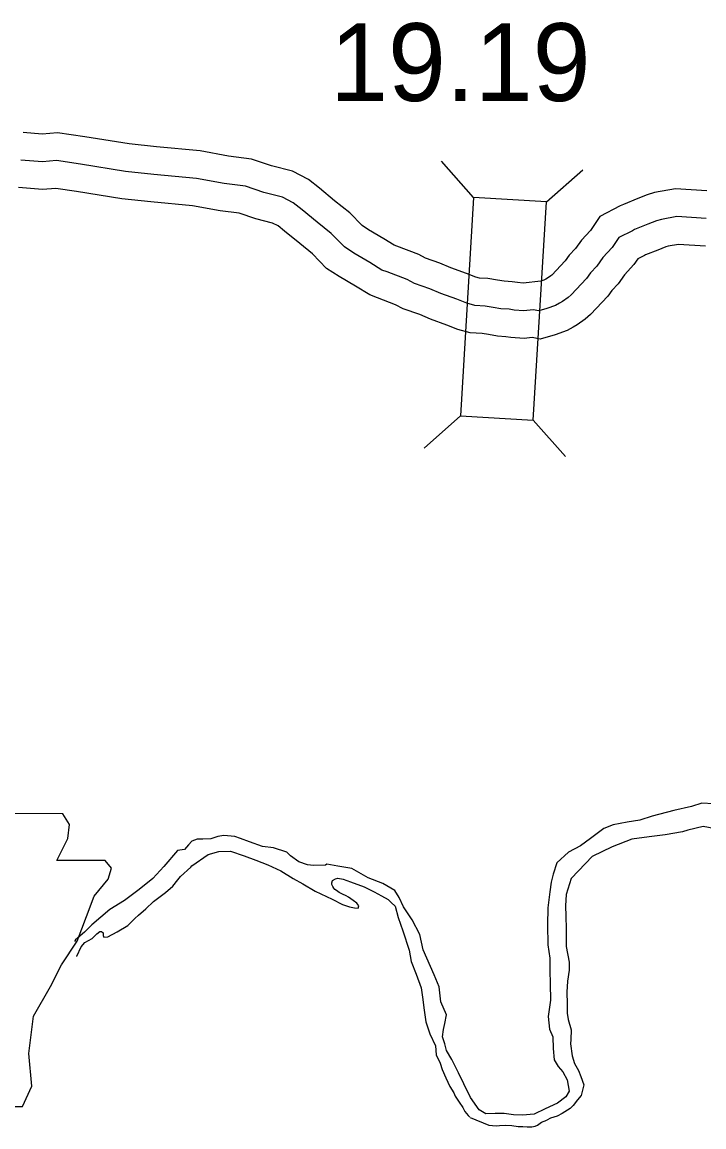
# Model space of a CAD drawing. Extents: x -83719 to 153526, y -11835 to 11446.
# Drawn here: x -4598 to -4474.7, y -2819.1 to -2619 of the extents above; entities that cross this region are included whole.
import ezdxf

# ---------------------------------------------------------------- set-up
doc = ezdxf.new("R2010")
doc.units = 0
for name, color, linetype in [('Level 10', 7, 'Continuous'), ('Level 20', 7, 'Continuous'), ('Level 21', 7, 'Continuous'), ('Level 58', 7, 'Continuous'), ('Level 59', 7, 'Continuous'), ('Level 9', 7, 'Continuous')]:
    doc.layers.add(name, color=color, linetype=linetype)

msp = doc.modelspace()

# ---------------------------------------------------------------- linework, layer by layer
at = {"layer": 'Level 10'}
for points in [[(-4474.15, -2649.59), (-4479.82, -2649.21), (-4483.58, -2649.87), (-4484.91, -2650.3), (-4486.63, -2650.97), (-4489.23, -2652.01), (-4489.85, -2652.3), (-4493.51, -2654.19), (-4495.21, -2656.72), (-4496.82, -2658.48), (-4497.93, -2660.03), (-4499.06, -2661.24), (-4499.78, -2662.23), (-4502.21, -2664.82), (-4502.35, -2664.95), (-4502.96, -2665.36), (-4503.28, -2665.55), (-4503.64, -2665.75), (-4504.17, -2665.95), (-4507.34, -2666.26), (-4508.42, -2666.18), (-4509.39, -2666.03), (-4510.82, -2665.94), (-4511.99, -2665.73), (-4513.74, -2665.46), (-4515.28, -2665.38), (-4515.94, -2665.18), (-4517.63, -2664.51), (-4520.44, -2663.52), (-4522.45, -2662.64), (-4525.02, -2661.77), (-4526.25, -2661.09), (-4530.21, -2659.56), (-4530.73, -2659.38), (-4532.55, -2658.25), (-4535.36, -2656.6), (-4536.52, -2655.84), (-4538.74, -2653.57), (-4541.48, -2651.36), (-4544.22, -2649.11), (-4546.19, -2647.53), (-4549.09, -2645.99), (-4552.9, -2645.04), (-4556.49, -2643.83), (-4560.68, -2643.28), (-4565.81, -2642.35), (-4573.7, -2641.61), (-4578.63, -2641.08), (-4586.67, -2639.8), (-4591.64, -2639.07), (-4594.36, -2639.31), (-4597.82, -2639.02)], [(-4474.38, -2659.59), (-4479.29, -2659.27), (-4481.14, -2659.59), (-4481.55, -2659.72), (-4482.98, -2660.28), (-4485.21, -2661.17), (-4485.39, -2661.26), (-4486.64, -2661.9), (-4487.33, -2662.93), (-4489.03, -2664.78), (-4490.18, -2666.4), (-4491.35, -2667.63), (-4492.06, -2668.61), (-4495.19, -2671.95), (-4496.13, -2672.8), (-4497.61, -2673.82), (-4498.3, -2674.22), (-4499.42, -2674.86), (-4501.56, -2675.64), (-4504.29, -2676.42), (-4505.75, -2676.15), (-4507.21, -2676.3), (-4509.58, -2676.13), (-4510.48, -2675.98), (-4512.03, -2675.89), (-4513.66, -2675.59), (-4514.77, -2675.42), (-4516.95, -2675.3), (-4519.21, -2674.65), (-4521.15, -2673.87), (-4524.11, -2672.83), (-4526.07, -2671.97), (-4529.06, -2670.96), (-4530.47, -2670.18), (-4533.72, -2668.93), (-4535.12, -2668.42), (-4537.72, -2666.81), (-4540.65, -2665.09), (-4542.92, -2663.6), (-4545.48, -2660.99), (-4547.8, -2659.11), (-4550.52, -2656.87), (-4551.7, -2655.93), (-4552.7, -2655.4), (-4555.72, -2654.64), (-4558.76, -2653.62), (-4562.21, -2653.17), (-4567.17, -2652.27), (-4574.71, -2651.56), (-4579.95, -2651), (-4588.18, -2649.68), (-4591.93, -2649.14), (-4594.34, -2649.35), (-4598.66, -2648.98)]]:
    msp.add_lwpolyline(points, dxfattribs=at)
at = {"layer": 'Level 20'}
for p, q in [((-4516.33, -2650.78), (-4522.17, -2644.19)), ((-4503.16, -2651.58), (-4496.57, -2645.74)), ((-4518.73, -2690.31), (-4525.31, -2696.14)), ((-4505.55, -2691.11), (-4499.72, -2697.69))]:
    msp.add_line(p, q, dxfattribs=at)
msp.add_lwpolyline([(-4505.55, -2691.11), (-4503.16, -2651.58), (-4516.33, -2650.78), (-4518.73, -2690.31)], close=True, dxfattribs=at)
at = {"layer": 'Level 21'}
msp.add_lwpolyline([(-4641.35, -2762.33), (-4638.82, -2779.25), (-4639.94, -2804.91), (-4637.69, -2806.32), (-4633.46, -2806.32), (-4633.46, -2815.34), (-4597.93, -2815.34), (-4596.24, -2811.68), (-4596.8, -2805.76), (-4595.96, -2798.99), (-4592.86, -2793.63), (-4590.88, -2789.68), (-4588.06, -2785.45), (-4586.37, -2780.94), (-4584.96, -2777.28), (-4582.42, -2774.17), (-4581.86, -2772.2), (-4582.99, -2770.79), (-4591.73, -2770.79), (-4589.75, -2766.84), (-4589.47, -2764.31), (-4590.64, -2762.36)], close=True, dxfattribs=at)
at = {"layer": 'Level 59'}
msp.add_lwpolyline([(-4474.26, -2654.59), (-4479.55, -2654.24), (-4482.36, -2654.73), (-4483.23, -2655.01), (-4484.8, -2655.62), (-4487.22, -2656.59), (-4487.62, -2656.78), (-4490.07, -2658.04), (-4491.27, -2659.82), (-4492.93, -2661.63), (-4494.05, -2663.22), (-4495.2, -2664.43), (-4495.92, -2665.42), (-4498.7, -2668.38), (-4499.24, -2668.87), (-4500.28, -2669.59), (-4500.79, -2669.88), (-4501.53, -2670.31), (-4503.1, -2670.88), (-4504.54, -2671.29), (-4505.54, -2671.11), (-4507.27, -2671.28), (-4509, -2671.15), (-4509.93, -2671.01), (-4511.43, -2670.92), (-4512.82, -2670.66), (-4514.25, -2670.44), (-4516.11, -2670.34), (-4517.57, -2669.92), (-4519.39, -2669.19), (-4522.27, -2668.17), (-4524.26, -2667.31), (-4527.04, -2666.36), (-4528.36, -2665.64), (-4531.97, -2664.25), (-4532.93, -2663.9), (-4535.14, -2662.53), (-4538.01, -2660.85), (-4539.72, -2659.72), (-4542.11, -2657.28), (-4544.64, -2655.23), (-4547.37, -2652.99), (-4548.95, -2651.73), (-4550.89, -2650.7), (-4554.31, -2649.84), (-4557.62, -2648.72), (-4561.44, -2648.23), (-4566.49, -2647.31), (-4574.2, -2646.59), (-4579.29, -2646.04), (-4587.43, -2644.74), (-4591.78, -2644.1), (-4594.35, -2644.33), (-4598.24, -2644)], dxfattribs=at)
at = {"layer": 'Level 9'}
for points in [[(-4472.96, -2760.56), (-4475.06, -2760.43), (-4476.93, -2761.06), (-4480.11, -2761.78), (-4484.02, -2762.79), (-4486.27, -2763.52), (-4488.54, -2763.88), (-4491.11, -2764.37), (-4492.78, -2765.05), (-4495.18, -2766.81), (-4497, -2768.18), (-4499.18, -2769.32), (-4501.28, -2771.25), (-4501.94, -2773.28), (-4502.3, -2774.71), (-4502.53, -2776.47), (-4502.88, -2779.37), (-4502.96, -2782.44), (-4502.88, -2786.08), (-4502.56, -2788.48), (-4502.56, -2790.72), (-4502.5, -2793.16), (-4502.42, -2796.09), (-4502.83, -2799.06), (-4502.6, -2801.36), (-4502.02, -2802.74), (-4501.93, -2804.88), (-4501.79, -2806.88), (-4501.01, -2808.1), (-4500.2, -2809.11), (-4499.42, -2810.52), (-4499.02, -2812.57), (-4499.67, -2813.62), (-4501.16, -2814.77), (-4503.37, -2815.77), (-4505.35, -2816.74), (-4507.48, -2816.9), (-4509.11, -2816.84), (-4510.81, -2816.65), (-4512.41, -2816.62), (-4514.14, -2816.66), (-4515.36, -2815.94), (-4516.89, -2813.72), (-4518.08, -2811.26), (-4519.08, -2809.28), (-4520.27, -2806.85), (-4521.25, -2805.2), (-4521.56, -2804), (-4521.97, -2802.76), (-4521.78, -2801.39), (-4521.53, -2800.33), (-4521.21, -2798.73), (-4522.24, -2796.41), (-4522.59, -2793.7), (-4523.49, -2791.52), (-4525.44, -2786.98), (-4526.07, -2784.2), (-4527.45, -2781.58), (-4529.01, -2779.19), (-4529.79, -2777.5), (-4530.56, -2776.22), (-4532.74, -2774.99), (-4535.42, -2773.94), (-4538.39, -2772.26), (-4540.88, -2771.85), (-4542.91, -2771.49), (-4543.11, -2771.65), (-4545.31, -2771.72), (-4546.41, -2771.6), (-4547.96, -2771.07), (-4549.48, -2769.95), (-4550.13, -2769.3), (-4552.52, -2768.5), (-4554.54, -2768.27), (-4556.86, -2767.46), (-4558.52, -2766.83), (-4559.51, -2766.49), (-4561.54, -2766.29), (-4562.61, -2766.5), (-4563.88, -2766.88), (-4565.31, -2766.96), (-4566.34, -2766.94), (-4567.32, -2767.29), (-4567.89, -2767.99), (-4568.64, -2768.81), (-4569.88, -2769.02), (-4572.35, -2771.92), (-4574.35, -2774.09), (-4576.82, -2776.05)], [(-4472.9, -2765), (-4474.83, -2764.63), (-4477.6, -2765.32), (-4478.54, -2765.64), (-4481.65, -2766.16), (-4484.55, -2766.55), (-4487.69, -2766.93), (-4491.27, -2768.34), (-4494.9, -2770.12), (-4497.37, -2772.68), (-4498.69, -2774.06), (-4499.61, -2776.99), (-4499.74, -2779.02), (-4499.64, -2780.89), (-4499.61, -2783.16), (-4499.59, -2786.4), (-4499.04, -2789.24), (-4499.03, -2790.68), (-4499.33, -2792.67), (-4499.46, -2794.64), (-4499.43, -2796.74), (-4499.42, -2798.45), (-4499.24, -2799.58), (-4498.71, -2801.49), (-4498.74, -2803.23), (-4498.81, -2803.99), (-4498.52, -2806.2), (-4498.07, -2807.58), (-4497.36, -2808.86), (-4496.91, -2809.9), (-4496.41, -2811.44), (-4496.9, -2813.37), (-4497.51, -2814.13), (-4498.33, -2815.18), (-4498.84, -2815.74), (-4500.29, -2816.62), (-4501.23, -2817.1), (-4502.43, -2817.45), (-4503.1, -2817.84)], [(-4588.17, -2788.22), (-4588.14, -2788.12), (-4587.34, -2786.43), (-4586.66, -2785.64), (-4585.35, -2784.93), (-4584.51, -2784.11), (-4583.93, -2783.65), (-4583.67, -2783.65), (-4583.37, -2783.92), (-4583.38, -2784.39), (-4583.22, -2784.69), (-4582.52, -2784.64), (-4580.84, -2783.76), (-4578.89, -2782.56), (-4577.64, -2781.31), (-4576.99, -2780.69), (-4575.61, -2779.58), (-4574.22, -2778.23), (-4572.06, -2776.6), (-4570.75, -2775.45), (-4569.83, -2774.33), (-4569.35, -2773.7), (-4567.49, -2772), (-4567.32, -2771.8), (-4564.36, -2769.74), (-4562.45, -2769.17), (-4560.29, -2769.11), (-4557.84, -2769.95), (-4555.75, -2770.78), (-4553.57, -2771.59), (-4551.19, -2772.66), (-4548.95, -2774.1), (-4547.23, -2775.02), (-4545.02, -2776.36), (-4541.95, -2777.84), (-4540.06, -2778.81), (-4538.77, -2779.23), (-4537.88, -2779.38), (-4537.21, -2779.42), (-4537.07, -2779.02), (-4537.49, -2778.52), (-4538.12, -2778.07), (-4538.94, -2777.46), (-4539.41, -2777.22), (-4540.07, -2776.91), (-4540.63, -2776.63), (-4541.12, -2776.22), (-4541.45, -2776.05), (-4541.61, -2775.81), (-4541.81, -2775.54), (-4542, -2775.14), (-4541.96, -2774.87), (-4541.86, -2774.41), (-4541.35, -2774.12), (-4540.88, -2774.02), (-4539.92, -2774.21), (-4538.6, -2774.66), (-4536.12, -2775.6), (-4534.3, -2776.46), (-4533.01, -2777.19)], [(-4576.82, -2776.05), (-4579.48, -2778.05), (-4582.17, -2779.7), (-4585.38, -2782.49), (-4586.73, -2783.77), (-4588.36, -2785.21), (-4588.55, -2785.46)], [(-4533.01, -2777.19), (-4531.79, -2777.87), (-4531.27, -2778.45), (-4530.51, -2779.09), (-4529.98, -2781.11), (-4529.15, -2783.55), (-4528.01, -2787.08), (-4527.64, -2789.08), (-4526.75, -2791.37), (-4525.82, -2793.85), (-4525.59, -2795.59), (-4525.26, -2797.93), (-4524.99, -2800.01), (-4524.26, -2802.19), (-4523.26, -2804.4), (-4523.09, -2806.01), (-4522.38, -2807.52), (-4522, -2808.66), (-4521.36, -2810.17), (-4520.65, -2811.72), (-4519.94, -2812.87), (-4519.65, -2813.47), (-4518.97, -2814.55), (-4518.29, -2815.56), (-4517.9, -2816.24), (-4517.34, -2816.98), (-4516.99, -2817.31)], [(-4516.95, -2817.35), (-4513.6, -2818.74), (-4512.23, -2818.88), (-4511.66, -2818.77), (-4510.53, -2818.74), (-4509.43, -2818.82), (-4508.29, -2818.97), (-4507.46, -2818.98), (-4506.62, -2819.03), (-4505.82, -2819.05), (-4505.19, -2818.94), (-4504.8, -2818.73), (-4504.07, -2818.18), (-4503.1, -2817.84)]]:
    msp.add_lwpolyline(points, dxfattribs=at)

# ---------------------------------------------------------------- texts
at = {"layer": 'Level 58'}
msp.add_text('19.19', height=14.08, dxfattribs=at).set_placement((-4542.3, -2633.3))

doc.saveas('drawing.dxf')
